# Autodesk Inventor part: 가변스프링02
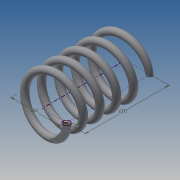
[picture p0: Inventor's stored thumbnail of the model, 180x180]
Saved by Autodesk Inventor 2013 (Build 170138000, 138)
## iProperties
Created: 2014-07
Part Number: 가변스프링02
Material: 일반
Document SubType Name: Modeling
Designer: SEMTLE01_MAIN
Density: 1 g/cm^3
Author: SEMTLE01_MAIN
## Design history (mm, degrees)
sketch "스케치1"
  geometry: L1 (0, 0)-(11, 0); L2 (11, 0)-(11, 36.411); L3 (11, 36.411)-(0, 36.411); L4 (0, 36.411)-(0, 0); C1 r 1.5 at (11, 0)
  constraints: 8 end point, 2 parallel, 1 centre point, 1 coincident, 1 horizontal, 1 perpendicular
  dimensions: "d0" = 3 diameter of C1; "d2" = 22 diameter of L1.end L4; "d3" = 36.4112 distance of L1.end L2.end (derived)
feature "코일1" pitch "d4" = 10; turns "d6" = 5; dims "d5" = 36.4112 (= d3), "d7" = 0, angle "d8" = 90 deg, angle "d9" = 90 deg, "d10" = 0, "d11" = 0
sketch "스케치2"
  geometry: L1 (-12.5, 0)-(-9.5, 0) reference; 1 further point
  constraints: 1 horizontal alignment
extrude "돌출1" cut sketch "스케치2" stored distance "d12" = 10; taper "d13" = 0 deg
node "작업 평면1"
sketch "스케치3"
  geometry: L1 (1.5, 0)-(-1.5, 0) reference; 1 further point
  constraints: 1 horizontal alignment
extrude "돌출2" cut sketch "스케치3" stored distance "d15" = 10; taper "d16" = 0 deg
node "솔리드1"
node "절단 모서리 투영1"
node "절단 모서리 투영2"
other parameters: "d14" = 0
